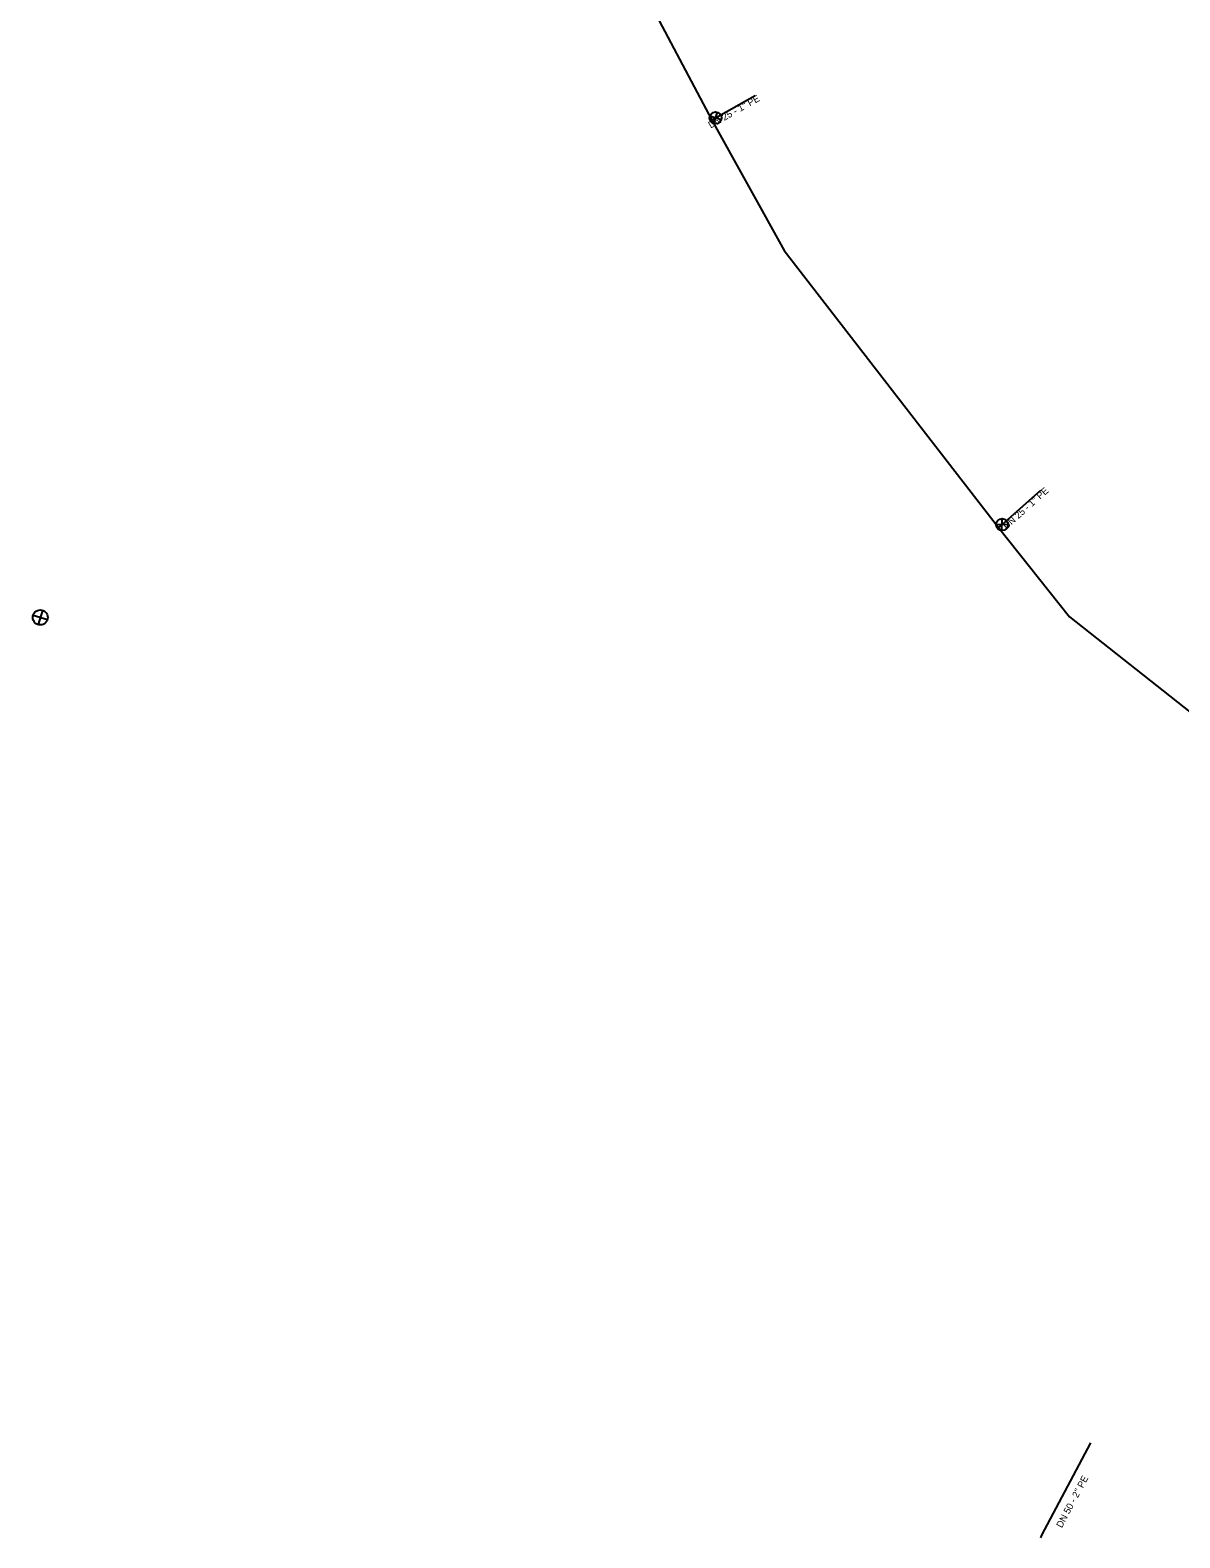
# Model space of a CAD drawing. Extents: x -443519 to -443021, y -1121477 to -1120870.
# Drawn here: x -443408.5 to -443331.7, y -1121278.9 to -1121178.2 of the extents above; entities that cross this region are included whole.
import ezdxf

# ---------------------------------------------------------------- set-up
doc = ezdxf.new("R2010")
doc.units = 0
for name, color, linetype in [('_pripojka_priblizne_', 7, 'Continuous'), ('_voda_smvak_prevzato_z_dokumentace_', 7, 'Continuous'), ('Default', 7, 'Continuous'), ('MoLevel 27', 7, 'Continuous'), ('MoLevel 32', 7, 'Continuous'), ('MoLevel 53', 7, 'Continuous')]:
    doc.layers.add(name, color=color, linetype=linetype)

# ---------------------------------------------------------------- blocks, each defined once
blk = doc.blocks.new('_uzaver_')
at = {"layer": 'Default'}
for p, q in [((-0.000035, -0.000035), (0.000035, 0.000035)), ((0.000035, -0.000035), (-0.000035, 0.000035))]:
    blk.add_line(p, q, dxfattribs=at)
for radius in [0.00005, 0.0000025]:
    blk.add_circle((0, 0), radius, dxfattribs=at)
blk = doc.blocks.new('_uzaver_pripojka_')
at = {"layer": 'Default'}
for p, q in [((-0.000035, -0.000035), (0.000035, 0.000035)), ((0.000035, -0.000035), (-0.000035, 0.000035))]:
    blk.add_line(p, q, dxfattribs=at)
for radius in [0.00005, 0.0000025]:
    blk.add_circle((0, 0), radius, dxfattribs=at)

msp = doc.modelspace()

# ---------------------------------------------------------------- linework, layer by layer
at = {"layer": '_pripojka_priblizne_'}
for points in [[(-443362.96, -1121184.21), (-443362.7, -1121184.06), (-443360.06, -1121182.57)], [(-443343.8, -1121211.41), (-443343.57, -1121211.22), (-443340.98, -1121208.91)], [(-443340.98, -1121278.89), (-443340.91, -1121278.72), (-443337.64, -1121272.54)]]:
    msp.add_lwpolyline(points, dxfattribs=at)
at = {"layer": '_voda_smvak_prevzato_z_dokumentace_'}
msp.add_lwpolyline([(-443385.18, -1121141.75), (-443377.04, -1121157.61), (-443362.96, -1121184.21), (-443358.12, -1121192.91), (-443343.8, -1121211.41), (-443339.07, -1121217.38), (-443321.16, -1121231.54), (-443310.84, -1121239.43)], dxfattribs=at)

# ---------------------------------------------------------------- block references
at = {"layer": 'MoLevel 27', "xscale": 10000, "yscale": 10000, "rotation": -152.0666112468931}
msp.add_blockref('_uzaver_', (-443407.8, -1121217.42), dxfattribs=at)
at = {"layer": 'MoLevel 53'}
for p, xscale, yscale, rotation in [((-443362.7, -1121184.06), 8000.000000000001, 8000, 28.057996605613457), ((-443343.57, -1121211.22), 7999.999999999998, 7999.999999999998, 43.808396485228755)]:
    msp.add_blockref('_uzaver_pripojka_', p, dxfattribs=dict(at, xscale=xscale, yscale=yscale, rotation=rotation))

# ---------------------------------------------------------------- texts
at = {"layer": 'MoLevel 32'}
for s, rotation, p in [("DN 25 - 1'' PE", 29.4859, (-443363.03, -1121184.77)), ("DN 25 - 1'' PE", 41.7771, (-443343.27, -1121211.56)), ("DN 50 - 2'' PE", 62.1192, (-443339.58, -1121278.26))]:
    msp.add_text(s, height=0.455, rotation=rotation, dxfattribs=at).set_placement(p)

doc.saveas('drawing.dxf')
